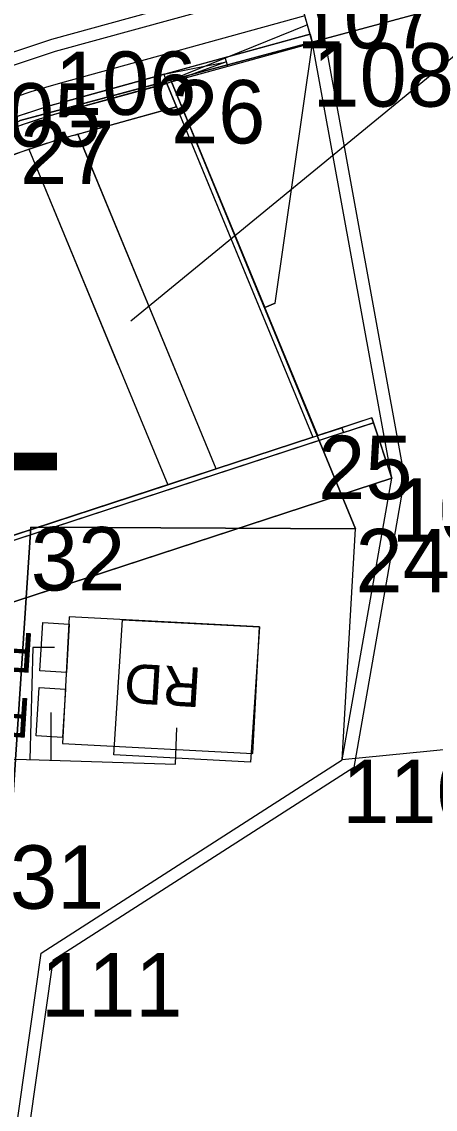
# Model space of a CAD drawing. Extents: x -728800 to -728100, y -1073200 to -1072700.
# Drawn here: x -728493.65 to -728487.13, y -1073043.53 to -1073026.38 of the extents above; entities that cross this region are included whole.
import ezdxf

# ---------------------------------------------------------------- set-up
doc = ezdxf.new("R2010")
doc.units = 0
for name, color, linetype in [('_NOR-návrh tenká', 7, 'Continuous'), ('_NOR-VDZ', 7, 'Continuous'), ('_NOR-šraf_+-0', 7, 'Continuous'), ('_NOR-šraf_+12', 7, 'Continuous'), ('_NOR-šraf_+6', 7, 'Continuous'), ('_NOR-šraf_bezbariéra', 7, 'Continuous'), ('_NOR-šraf_chodník', 7, 'Continuous'), ('_NOR-šraf_signální pás', 7, 'Continuous'), ('_NOR-šraf_varovný pás', 7, 'Continuous'), ('_NOR-šraf_vozovka', 7, 'Continuous'), ('_NOR-šraf_zeleň', 7, 'Continuous'), ('A1_OBVOD Spravy železnic', 7, 'Continuous'), ('A2_OBVOD STAVBY', 7, 'Continuous'), ('B1_body_poloha', 7, 'Continuous'), ('B2_body_číslo', 7, 'Continuous'), ('K_01_Hranice parcel', 7, 'Continuous'), ('KOS_kabelová trasa', 7, 'Continuous'), ('KOS_nové prvky PZZ', 7, 'Continuous'), ('KTA_PZZ rušené', 7, 'Continuous'), ('KTA_členění PS a SO', 7, 'Continuous'), ('ZA_01_Trvalý_pro_SŽDC_dle_UMVZST', 7, 'Continuous'), ('ZA_02_Dočasný_do_1_roku', 7, 'Continuous')]:
    doc.layers.add(name, color=color, linetype=linetype)

msp = doc.modelspace()

# ---------------------------------------------------------------- linework, layer by layer
at = {"layer": '_NOR-návrh tenká'}
for p, q in [((-728489.66, -1073030.819), (-728489.068, -1073026.719)), ((-728489.068, -1073026.719), (-728489.108, -1073026.574)), ((-728491.408, -1073027.208), (-728490.424, -1073027.015)), ((-728490.424, -1073027.015), (-728491.368, -1073027.353)), ((-728490.404, -1073027.087), (-728490.444, -1073026.942)), ((-728491.368, -1073027.353), (-728491.408, -1073027.208)), ((-728491.368, -1073027.353), (-728489.062, -1073032.933)), ((-728492.771, -1073028.155), (-728491.091, -1073032.219)), ((-728493.539, -1073028.392), (-728492.136, -1073031.786)), ((-728489.66, -1073030.819), (-728489.821, -1073030.886)), ((-728488.131, -1073032.628), (-728487.82, -1073033.579))]:
    msp.add_line(p, q, dxfattribs=at)
for points in [[(-728489.108, -1073026.574), (-728489.188, -1073026.285), (-728493.044, -1073027.348)], [(-728489.108, -1073026.574), (-728492.964, -1073027.637)], [(-728489.068, -1073026.719), (-728492.924, -1073027.782)], [(-728488.985, -1073032.908), (-728491.29, -1073027.331)], [(-728491.214, -1073027.725), (-728492.818, -1073028.168)], [(-728488.106, -1073032.704), (-728496.63, -1073035.493)], [(-728488.131, -1073032.628), (-728488.985, -1073032.908)], [(-728489.062, -1073032.933), (-728496.655, -1073035.417)], [(-728487.82, -1073033.579), (-728495.393, -1073036.056)]]:
    msp.add_lwpolyline(points, dxfattribs=at)
for radius, end in [(12.3, 176.1779), (12, 176.2645), (11.85, 176.3095), (11.45, 117.2893)]:
    msp.add_arc((-728489.773, -1073039.206), radius, 105.42, end, dxfattribs=at)
at = {"layer": '_NOR-VDZ'}
msp.add_line((-728489.148, -1073026.429), (-728491.302, -1073027.301), dxfattribs=at)
at = {"layer": '_NOR-šraf_+-0'}
for points in [[(-728488.985, -1073032.908), (-728491.29, -1073027.331), (-728491.368, -1073027.353), (-728491.214, -1073027.725), (-728489.062, -1073032.933), (-728488.985, -1073032.908)], [(-728488.581, -1073032.86), (-728488.106, -1073032.704), (-728488.131, -1073032.628), (-728488.606, -1073032.784), (-728488.581, -1073032.86)]]:
    msp.add_lwpolyline(points, dxfattribs=at)
at = {"layer": '_NOR-šraf_+12'}
msp.add_lwpolyline([(-728490.444, -1073026.942), (-728489.108, -1073026.574), (-728489.068, -1073026.719), (-728490.404, -1073027.087), (-728490.424, -1073027.015), (-728490.444, -1073026.942)], dxfattribs=at)
at = {"layer": '_NOR-šraf_+6'}
msp.add_lwpolyline([(-728496.655, -1073035.417), (-728491.352, -1073033.682), (-728490.59, -1073033.433), (-728489.062, -1073032.933), (-728488.985, -1073032.908), (-728488.606, -1073032.784), (-728488.594, -1073032.822), (-728488.581, -1073032.86), (-728496.554, -1073035.468), (-728496.63, -1073035.493), (-728496.655, -1073035.417), (-728496.655, -1073035.417)], dxfattribs=at)
at = {"layer": '_NOR-šraf_bezbariéra'}
msp.add_lwpolyline([(-728492.924, -1073027.782), (-728491.368, -1073027.353), (-728491.408, -1073027.208), (-728492.964, -1073027.637)], dxfattribs=at)
for radius in [12, 11.85]:
    msp.add_arc((-728489.773, -1073039.206), radius, 105.42, 117.0974, dxfattribs=at)
at = {"layer": '_NOR-šraf_chodník'}
for p, q in [((-728493.539, -1073028.392), (-728491.352, -1073033.682)), ((-728491.352, -1073033.682), (-728496.655, -1073035.417))]:
    msp.add_line(p, q, dxfattribs=at)
msp.add_lwpolyline([(-728490.59, -1073033.433), (-728492.771, -1073028.155), (-728491.214, -1073027.725), (-728489.062, -1073032.933), (-728490.59, -1073033.433)], dxfattribs=at)
msp.add_arc((-728489.773, -1073039.206), 11.45, 109.1994, 117.2893, dxfattribs=at)
at = {"layer": '_NOR-šraf_signální pás'}
for points in [[(-728490.59, -1073033.433), (-728492.771, -1073028.155), (-728492.818, -1073028.168)], [(-728493.539, -1073028.392), (-728491.352, -1073033.682), (-728490.59, -1073033.433), (-728490.59, -1073033.433)]]:
    msp.add_lwpolyline(points, dxfattribs=at)
msp.add_arc((-728489.773, -1073039.206), 11.45, 105.42, 109.1994, dxfattribs=at)
at = {"layer": '_NOR-šraf_varovný pás'}
msp.add_lwpolyline([(-728492.818, -1073028.168), (-728492.771, -1073028.155), (-728491.214, -1073027.725), (-728491.368, -1073027.353), (-728492.924, -1073027.782)], dxfattribs=at)
for radius, start, end in [(11.85, 105.42, 117.0974), (11.45, 105.42, 109.1994), (11.45, 109.1994, 117.2893)]:
    msp.add_arc((-728489.773, -1073039.206), radius, start, end, dxfattribs=at)
at = {"layer": '_NOR-šraf_vozovka'}
for p, q in [((-728489.188, -1073026.285), (-728493.044, -1073027.348)), ((-728489.108, -1073026.574), (-728489.188, -1073026.285)), ((-728491.408, -1073027.208), (-728489.108, -1073026.574)), ((-728492.964, -1073027.637), (-728491.408, -1073027.208))]:
    msp.add_line(p, q, dxfattribs=at)
for radius, end in [(12.3, 176.1779), (12, 117.0974)]:
    msp.add_arc((-728489.773, -1073039.206), radius, 105.42, end, dxfattribs=at)
at = {"layer": '_NOR-šraf_zeleň'}
for p, q in [((-728488.106, -1073032.704), (-728496.554, -1073035.468)), ((-728487.82, -1073033.579), (-728488.106, -1073032.704)), ((-728495.393, -1073036.056), (-728487.82, -1073033.579))]:
    msp.add_line(p, q, dxfattribs=at)
msp.add_lwpolyline([(-728489.821, -1073030.886), (-728489.66, -1073030.819), (-728489.068, -1073026.719), (-728490.404, -1073027.087), (-728491.29, -1073027.331), (-728489.821, -1073030.886), (-728489.821, -1073030.886)], dxfattribs=at)
at = {"layer": 'A1_OBVOD Spravy železnic'}
msp.add_lwpolyline([(-728503.24, -1073052.34), (-728501.19, -1073037.94), (-728499.78, -1073032.61), (-728497.54, -1073030.15), (-728493.68, -1073027.94), (-728443.97, -1073014.59), (-728443.68, -1073014.51), (-728441.09, -1073023.23), (-728428.92, -1073019.94), (-728429.82, -1073016.43), (-728427.49, -1073015.84), (-728421.24, -1073014.23), (-728422.34, -1073010.27), (-728422.77, -1073008.34), (-728418.21, -1073007), (-728380.57, -1072997.2), (-728343.1, -1072987.57), (-728330.49, -1072984.52), (-728326.79, -1072988.95)], dxfattribs=at)
at = {"layer": 'A2_OBVOD STAVBY'}
for points in [[(-728488.873, -1073026.674), (-728489.181, -1073025.557), (-728493.185, -1073026.66), (-728494.705, -1073027.164), (-728496.389, -1073027.993), (-728498.589, -1073029.657), (-728499.85, -1073030.989), (-728500.962, -1073032.598), (-728501.8, -1073034.243), (-728502.009, -1073034.876), (-728501.833, -1073035.753)], [(-728488.873, -1073026.674), (-728487.617, -1073033.578), (-728488.418, -1073038.141), (-728493.164, -1073041.187), (-728493.918, -1073046.515)]]:
    msp.add_lwpolyline(points, dxfattribs=at)
at = {"layer": 'B1_body_poloha'}
for p, q in [((-728489.07, -1073026.72), (-728489.07, -1073026.72)), ((-728493.13, -1073026.85), (-728493.13, -1073026.85)), ((-728491.3, -1073027.3), (-728491.3, -1073027.3)), ((-728488.98, -1073032.91), (-728488.98, -1073032.91)), ((-728487.82, -1073033.58), (-728487.82, -1073033.58)), ((-728493.51, -1073034.35), (-728493.51, -1073034.35)), ((-728488.39, -1073034.38), (-728488.39, -1073034.38)), ((-728488.6, -1073038.02), (-728488.6, -1073038.02)), ((-728493.35, -1073041.07), (-728493.35, -1073041.07))]:
    msp.add_line(p, q, dxfattribs=at)
at = {"layer": 'K_01_Hranice parcel'}
for points in [[(-728443.97, -1073014.59), (-728493.68, -1073027.94), (-728497.54, -1073030.15), (-728499.78, -1073032.61)], [(-728428.94, -1073031.04), (-728435.33, -1073031.82), (-728462.29, -1073035.43), (-728488.6, -1073038.02), (-728488.39, -1073034.38), (-728493.51, -1073034.35), (-728493.84, -1073039.37)]]:
    msp.add_lwpolyline(points, dxfattribs=at)
at = {"layer": 'KOS_kabelová trasa'}
for points in [[(-728493.135, -1073036.249), (-728493.478, -1073036.249), (-728493.524, -1073038.017)], [(-728493.194, -1073037.275), (-728493.194, -1073038.027)], [(-728495.185, -1073037.974), (-728493.377, -1073038.021), (-728491.229, -1073038.09), (-728491.21, -1073037.515)]]:
    msp.add_lwpolyline(points, dxfattribs=at)
at = {"layer": 'KOS_nové prvky PZZ'}
for points in [[(-728489.907, -1073035.925), (-728492.903, -1073035.767), (-728493.008, -1073037.764), (-728490.012, -1073037.922)], [(-728493.32, -1073035.857), (-728492.904, -1073035.883), (-728492.95, -1073036.642), (-728493.366, -1073036.616)], [(-728493.379, -1073036.883), (-728492.963, -1073036.908), (-728493.009, -1073037.667), (-728493.425, -1073037.641)]]:
    msp.add_lwpolyline(points, close=True, dxfattribs=at)
at = {"layer": 'KTA_PZZ rušené'}
msp.add_lwpolyline([(-728490.044, -1073038.056), (-728492.203, -1073037.942), (-728492.066, -1073035.811), (-728489.907, -1073035.925), (-728490.044, -1073038.056)], dxfattribs=at)
at = {"layer": 'KTA_členění PS a SO'}
msp.add_line((-728484.574, -1073025.064), (-728491.931, -1073031.102), dxfattribs=at)
at = {"layer": 'ZA_01_Trvalý_pro_SŽDC_dle_UMVZST'}
msp.add_lwpolyline([(-728500.719, -1073036.161), (-728501.19, -1073037.94), (-728493.84, -1073039.37), (-728493.51, -1073034.35), (-728488.39, -1073034.38), (-728491.302, -1073027.301), (-728493.68, -1073027.94), (-728497.54, -1073030.15), (-728499.78, -1073032.61)], close=True, dxfattribs=at)
at = {"layer": 'ZA_02_Dočasný_do_1_roku'}
for points in [[(-728494.117, -1073046.49), (-728493.349, -1073041.068), (-728488.6, -1073038.02), (-728487.82, -1073033.579), (-728489.068, -1073026.719), (-728489.321, -1073025.803), (-728493.127, -1073026.851), (-728494.629, -1073027.35)], [(-728493.68, -1073027.94), (-728491.302, -1073027.301), (-728488.39, -1073034.38), (-728493.51, -1073034.35), (-728493.84, -1073039.37)]]:
    msp.add_lwpolyline(points, dxfattribs=at)

# ---------------------------------------------------------------- texts
at = {"layer": 'B2_body_číslo'}
for s, p in [('107', (-728489.32, -1073026.8)), ('108', (-728489.07, -1073027.72)), ('106', (-728493.13, -1073027.85)), ('105', (-728494.63, -1073028.35)), ('26', (-728491.3, -1073028.3)), ('27', (-728493.68, -1073028.94)), ('25', (-728488.98, -1073033.91)), ('109', (-728487.82, -1073034.58)), ('32', (-728493.51, -1073035.35)), ('24', (-728488.39, -1073035.38)), ('110', (-728488.6, -1073039.02)), ('31', (-728493.84, -1073040.37)), ('111', (-728493.35, -1073042.07))]:
    msp.add_text(s, height=1, dxfattribs=at).set_placement(p)
at = {"layer": 'KOS_nové prvky PZZ'}
for s, rotation, p in [('RVO', 176.3219, (-728493.438, -1073036.029)), ('RD', 176.5903, (-728490.809, -1073036.57)), ('RP1+T+SMO', 176.3219, (-728493.497, -1073037.054))]:
    msp.add_text(s, height=0.625, rotation=rotation, dxfattribs=at).set_placement(p)
at = {"layer": 'ZA_01_Trvalý_pro_SŽDC_dle_UMVZST'}
msp.add_text('T2', height=2.5, rotation=180, dxfattribs=at).set_placement((-728493.022, -1073030.953))

doc.saveas('drawing.dxf')
